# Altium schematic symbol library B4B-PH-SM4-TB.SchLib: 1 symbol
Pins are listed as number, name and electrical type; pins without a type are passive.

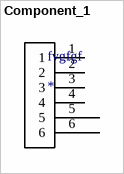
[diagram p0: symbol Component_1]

## Component_1
designator fvgfgf
footprint jst4pin
pins: 1, 2, 3, 4, 5, 6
